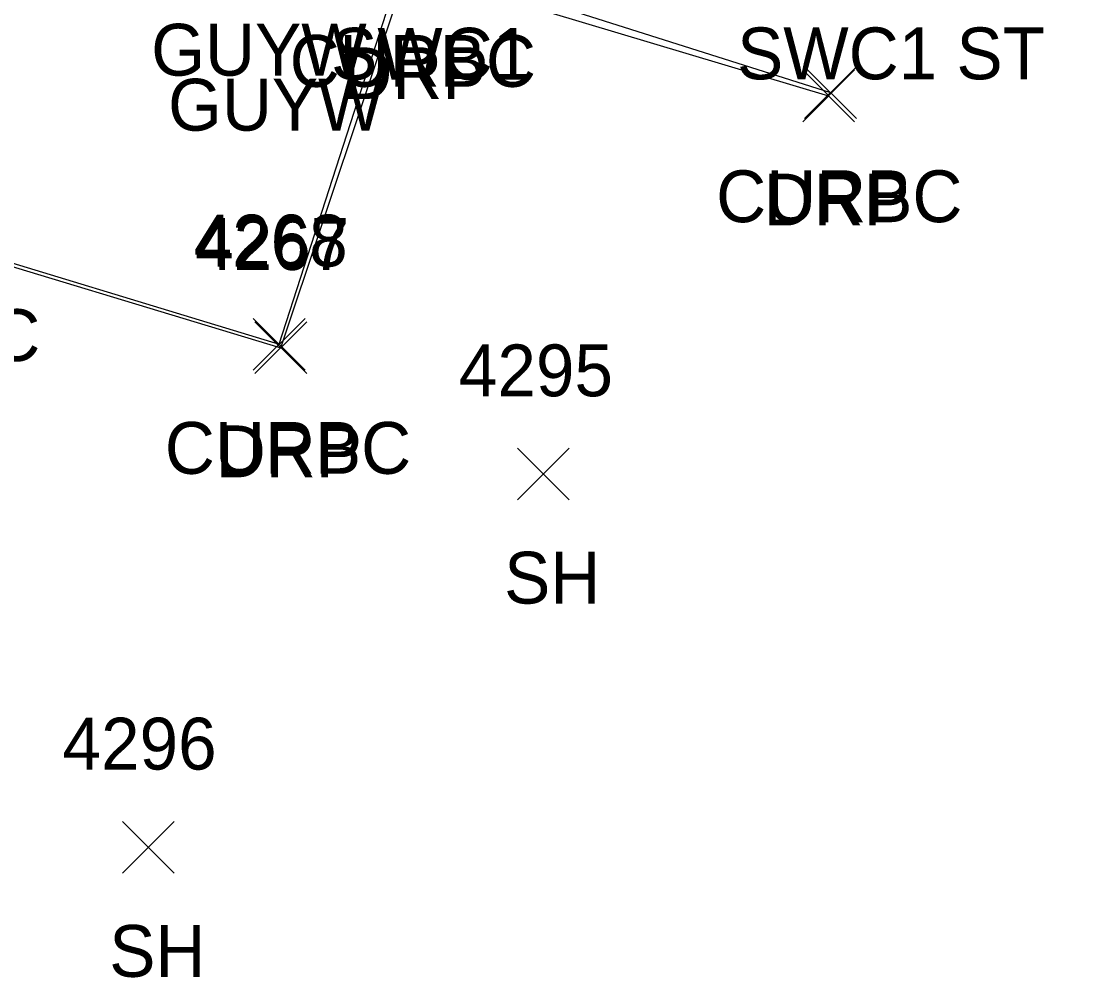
# Model space of a CAD drawing. Extents: x 1653135 to 1655489, y 602711 to 605684.
# Drawn here: x 1653367.22 to 1653408.55, y 604945.69 to 604982.59 of the extents above; entities that cross this region are included whole.
import ezdxf

# ---------------------------------------------------------------- set-up
doc = ezdxf.new("R2010")
doc.units = 0
for name, color, linetype in [('L_A', 7, 'Continuous'), ('L_I', 7, 'Continuous'), ('L_TIC', 7, 'Continuous'), ('R_A', 7, 'Continuous'), ('R_I', 7, 'Continuous'), ('R_TIC', 7, 'Continuous'), ('RC', 7, 'Continuous'), ('RDP', 7, 'Continuous'), ('U_A', 7, 'Continuous')]:
    doc.layers.add(name, color=color, linetype=linetype)

msp = doc.modelspace()

# ---------------------------------------------------------------- linework, layer by layer
at = {"layer": 'L_TIC'}
for points in [[(1653386.374, 604964.126), (1653388.374, 604966.126)], [(1653388.374, 604964.126), (1653386.374, 604966.126)], [(1653386.374, 604964.126), (1653388.374, 604966.126)], [(1653388.374, 604964.126), (1653386.374, 604966.126)], [(1653371.126, 604949.721), (1653373.126, 604951.721)], [(1653373.126, 604949.721), (1653371.126, 604951.721)], [(1653371.126, 604949.721), (1653373.126, 604951.721)], [(1653373.126, 604949.721), (1653371.126, 604951.721)]]:
    msp.add_lwpolyline(points, dxfattribs=at)
at = {"layer": 'R_TIC'}
for points in [[(1653397.392, 604978.719), (1653399.392, 604980.719)], [(1653399.392, 604978.719), (1653397.392, 604980.719)], [(1653397.392, 604978.719), (1653399.392, 604980.719)], [(1653399.392, 604978.719), (1653397.392, 604980.719)], [(1653397.467, 604978.845), (1653399.467, 604980.845)], [(1653399.467, 604978.845), (1653397.467, 604980.845)], [(1653397.467, 604978.845), (1653399.467, 604980.845)], [(1653399.467, 604978.845), (1653397.467, 604980.845)], [(1653376.178, 604969.134), (1653378.178, 604971.134)], [(1653378.178, 604969.134), (1653376.178, 604971.134)], [(1653376.178, 604969.134), (1653378.178, 604971.134)], [(1653378.178, 604969.134), (1653376.178, 604971.134)], [(1653376.239, 604969.001), (1653378.239, 604971.001)], [(1653378.239, 604969.001), (1653376.239, 604971.001)], [(1653376.239, 604969.001), (1653378.239, 604971.001)], [(1653378.239, 604969.001), (1653376.239, 604971.001)]]:
    msp.add_lwpolyline(points, dxfattribs=at)
at = {"layer": 'RC'}
msp.add_lwpolyline([(1653461.112, 605032.534), (1653449.922, 605049.198), (1653443.907, 605057.821), (1653441.507, 605059.753), (1653437.992, 605060.258), (1653434.799, 605059.429), (1653430.986, 605057.43), (1653410.367, 605039.832), (1653392.919, 605023.548), (1653372.22, 605001.751), (1653359.36, 604987.685), (1653357.701, 604983.998), (1653357.899, 604980.417), (1653359.903, 604976.693), (1653362.858, 604974.486), (1653377.178, 604970.134), (1653381.999, 604985.069), (1653398.467, 604979.845)], dxfattribs=at)
at = {"layer": 'RDP'}
msp.add_lwpolyline([(1653359.179, 604987.803), (1653357.514, 604984.058), (1653357.685, 604980.334), (1653359.785, 604976.668), (1653362.771, 604974.374), (1653377.239, 604970.001), (1653382.123, 604984.594), (1653398.392, 604979.719)], dxfattribs=at)

# ---------------------------------------------------------------- texts
at = {"layer": 'L_A'}
for p in [(1653385.862, 604960.126), (1653385.862, 604960.126), (1653370.614, 604945.721), (1653370.614, 604945.721)]:
    msp.add_text('SH', height=2, dxfattribs=at).set_placement(p)
at = {"layer": 'L_I'}
for s, p in [('4295', (1653384.115, 604968.126)), ('4295', (1653384.115, 604968.126)), ('4296', (1653368.811, 604953.721)), ('4296', (1653368.811, 604953.721))]:
    msp.add_text(s, height=2, dxfattribs=at).set_placement(p)
at = {"layer": 'R_A'}
for s, p in [('SWC1', (1653379.18, 604980.345)), ('SWC1', (1653379.18, 604980.345)), ('SWC1 ST', (1653394.858, 604980.359)), ('SWC1 ST', (1653394.858, 604980.359)), ('CURBC', (1653377.581, 604980.069)), ('CURBC', (1653377.581, 604980.069)), ('DRP', (1653379.612, 604979.594)), ('DRP', (1653379.612, 604979.594)), ('CURBC', (1653394.049, 604974.845)), ('CURBC', (1653394.049, 604974.845)), ('DRP', (1653395.88, 604974.719)), ('DRP', (1653395.88, 604974.719)), ('CURBC', (1653358.441, 604969.486)), ('CURBC', (1653358.441, 604969.486)), ('CURBC', (1653372.761, 604965.134)), ('CURBC', (1653372.761, 604965.134)), ('DRP', (1653374.727, 604965.001)), ('DRP', (1653374.727, 604965.001))]:
    msp.add_text(s, height=2, dxfattribs=at).set_placement(p)
at = {"layer": 'R_I'}
for s, p in [('4268', (1653373.871, 604973.134)), ('4268', (1653373.871, 604973.134)), ('4267', (1653373.932, 604973.001)), ('4267', (1653373.932, 604973.001))]:
    msp.add_text(s, height=2, dxfattribs=at).set_placement(p)
at = {"layer": 'U_A'}
for p in [(1653372.234, 604980.5), (1653372.886, 604978.378)]:
    msp.add_text('GUYW', height=2, dxfattribs=at).set_placement(p)

doc.saveas('drawing.dxf')
